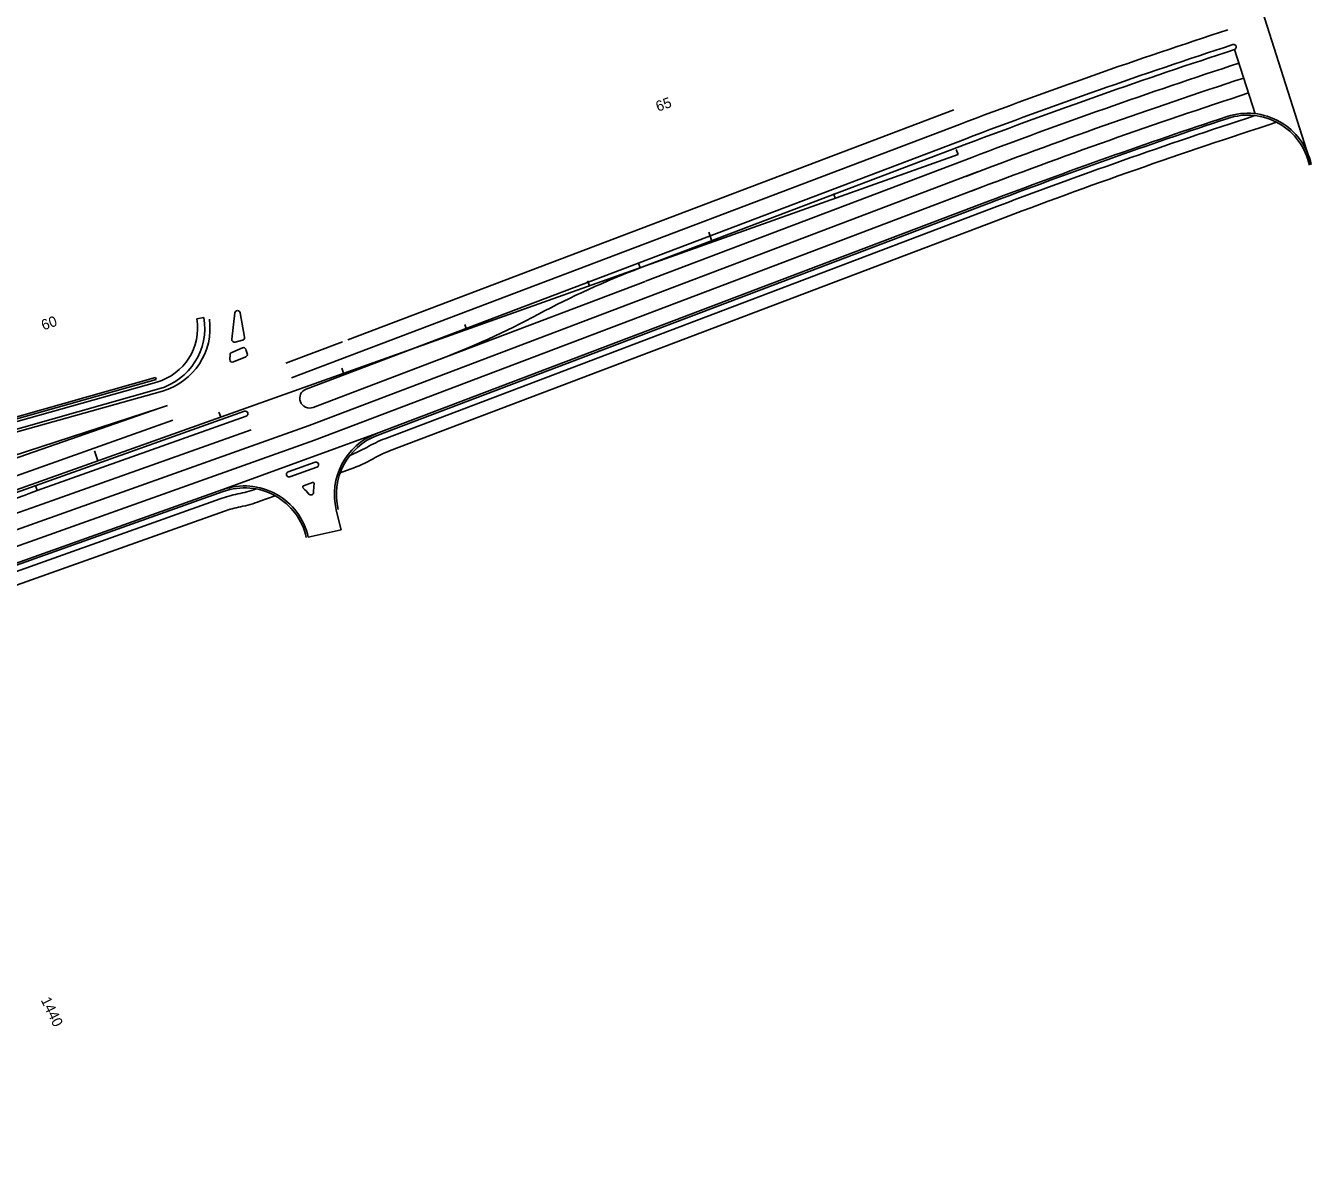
# Model space of a CAD drawing. Extents: x 2339272 to 2351734, y 366540 to 375057.
# Drawn here: x 2350276 to 2351261, y 367900 to 368767 of the extents above; entities that cross this region are included whole.
import ezdxf

# ---------------------------------------------------------------- set-up
doc = ezdxf.new("R2010")
doc.units = 0
for name, color, linetype in [('RD_HC_Cl', 7, 'Continuous'), ('RD_HC_Data_Tic', 7, 'Continuous'), ('RD_HC_TX_Sta50', 7, 'Continuous'), ('RD_PD_ConcMed', 7, 'Continuous'), ('RD_PD_Final_LnLine', 7, 'Continuous'), ('RD_PD_Final_TrvlWay', 7, 'Continuous'), ('RD_PD_FOC', 7, 'Continuous'), ('RD_PD_NOISE-WALL-GM', 7, 'Continuous'), ('RD_PD_SW', 7, 'Continuous')]:
    doc.layers.add(name, color=color, linetype=linetype)

msp = doc.modelspace()

# ---------------------------------------------------------------- linework, layer by layer
at = {"layer": 'RD_HC_Cl'}
msp.add_line((2350026.96, 368325.73), (2350990.33, 368668.55), dxfattribs=at)
msp.add_arc((2351779.88, 368732.45), 1762, 199.58804, 235.18078, dxfattribs=at)
at = {"layer": 'RD_HC_Data_Tic'}
for p, q in [((2350990.33, 368668.55), (2350988.99, 368672.32)), ((2350896.12, 368635.02), (2350894.78, 368638.79)), ((2350801.9, 368601.5), (2350799.22, 368609.04)), ((2350707.69, 368567.97), (2350706.35, 368571.74)), ((2350613.48, 368534.45), (2350612.14, 368538.22)), ((2350519.27, 368500.92), (2350517.92, 368504.69)), ((2350425.05, 368467.4), (2350423.71, 368471.17)), ((2350330.84, 368433.87), (2350328.16, 368441.41))]:
    msp.add_line(p, q, dxfattribs=at)
at = {"layer": 'RD_PD_ConcMed'}
for p, q in [((2350745.27, 368585.41), (2350746.69, 368581.67)), ((2350433.58, 368527.01), (2350435.96, 368547.18)), ((2350443.28, 368528.49), (2350439.91, 368547.3)), ((2350436.03, 368524.83), (2350441.77, 368526.19)), ((2350433.47, 368516.9), (2350441.62, 368520.42)), ((2350444.31, 368519.23), (2350445.39, 368516.06)), ((2350432.27, 368515.19), (2350432.04, 368511.5)), ((2350434.82, 368509.53), (2350444.28, 368513.57)), ((2350284.45, 368411), (2350283.11, 368414.76))]:
    msp.add_line(p, q, dxfattribs=at)
for centre, start, end in [((2350437.95, 368546.95), 10.1289, 173.26408), ((2350435.56, 368526.78), 173.26408, 283.35584), ((2350441.31, 368528.14), 283.35584, 10.1289), ((2350434.27, 368515.06), 113.39418, 176.37352), ((2350442.41, 368518.59), 18.8959, 113.39418), ((2350434.03, 368511.37), 176.37352, 293.08849), ((2350443.5, 368515.41), 293.08849, 18.8959)]:
    msp.add_arc(centre, 2, start, end, dxfattribs=at)
at = {"layer": 'RD_PD_Final_LnLine'}
for p, q in [((2351202.2, 368749), (2351218.22, 368699.85)), ((2350522.45, 368526.52), (2350987.15, 368702.86)), ((2350479.23, 368497.29), (2350991.4, 368691.65)), ((2350490.5, 368488.73), (2350995.66, 368680.43)), ((2350746.69, 368581.67), (2350997.08, 368676.69)), ((2350750.6, 368571.39), (2351000.98, 368666.4)), ((2350492.88, 368460.75), (2351005.24, 368655.18)), ((2350497.02, 368449.49), (2351009.5, 368643.96)), ((2350590.4, 368510.59), (2350750.54, 368571.36)), ((2350474.98, 368508.51), (2350518.4, 368524.98)), ((2350495.82, 368474.7), (2350590.4, 368510.59)), ((2350058.41, 368334.8), (2350443.27, 368471.76)), ((2350284.45, 368411), (2350444.62, 368467.99)), ((2350378.1, 368474.04), (2350384.24, 368476.22)), ((2350023.6, 368335.16), (2350388.26, 368464.92)), ((2350036.68, 368298.41), (2350492.88, 368460.75)), ((2350288.14, 368400.63), (2350448.3, 368457.63)), ((2350040.7, 368287.11), (2350497.02, 368449.49)), ((2350126.71, 368343.19), (2350288.14, 368400.63))]:
    msp.add_line(p, q, dxfattribs=at)
for centre, radius, start, end in [((2352620.61, 364398.39), 4591.99, 108.05731, 110.78079), ((2352620.61, 364398.39), 4579.99, 108.05731, 110.78079), ((2351201.58, 368750.9), 2, 288.05731, 110.01232), ((2352620.61, 364398.39), 4575.99, 108.05731, 110.78079), ((2352620.61, 364398.39), 4564.99, 108.05731, 110.78079), ((2352620.61, 364398.39), 4552.99, 108.05731, 110.9012), ((2352620.61, 364398.39), 4540.99, 108.05731, 110.90467), ((2350984.41, 367955.26), 670, 110.78079, 118.12726), ((2350352.69, 369137.01), 670, 290.78079, 298.12726), ((2350493.16, 368481.72), 7.5, 110.78079, 200.78079), ((2350493.16, 368481.72), 7.5, 200.78079, 290.78079), ((2350443.93, 368469.87), 2, 289.58772, 109.14219), ((2350509.07, 367779.77), 670, 109.58804, 116.93451), ((2351779.88, 368732.45), 1762, 199.58804, 235.18078)]:
    msp.add_arc(centre, radius, start, end, dxfattribs=at)
at = {"layer": 'RD_PD_Final_TrvlWay'}
for p, q in [((2351215.26, 368804.68), (2351261.14, 368660.83)), ((2350544.45, 368454.65), (2351013.75, 368632.74)), ((2350098.11, 368408.37), (2350380.3, 368487.28)), ((2350106.54, 368385.9), (2350378.1, 368474.04)), ((2350108.55, 368380.24), (2350378.1, 368474.04)), ((2350476.73, 368425.28), (2350497.49, 368432.67)), ((2350478.07, 368421.52), (2350498.83, 368428.9)), ((2350157.62, 368315.98), (2350426.54, 368411.67)), ((2350488.54, 368414.63), (2350495.36, 368417.05)), ((2350517.3, 368380.9), (2350513.61, 368396.08)), ((2350492.13, 368375.34), (2350517.3, 368380.9))]:
    msp.add_line(p, q, dxfattribs=at)
for centre, radius, start, end in [((2352620.61, 364398.39), 4528.99, 108.32637, 110.78079), ((2351212.28, 368650.21), 50, 12.2663, 108.32637), ((2350366.84, 368535.44), 50, 285.62317, 8.00142), ((2350562.19, 368407.91), 50, 110.78079, 193.67822), ((2350498.16, 368430.79), 2, 289.58804, 109.58804), ((2350477.4, 368423.4), 2, 109.58804, 289.58804), ((2350443.3, 368364.56), 50, 12.44954, 109.58804), ((2350488.87, 368413.68), 1, 109.58804, 227.14864), ((2350443.3, 368364.56), 66, 41.52414, 47.14864), ((2350494.21, 368409.64), 2, 221.52414, 358.53457), ((2350495.7, 368416.11), 1, 352.96368, 109.58804), ((2350562.19, 368407.91), 66, 172.96368, 178.53457)]:
    msp.add_arc(centre, radius, start, end, dxfattribs=at)
at = {"layer": 'RD_PD_FOC'}
for p, q in [((2350544.98, 368453.25), (2351014.29, 368631.34)), ((2350098.03, 368409.94), (2350377.52, 368488.89)), ((2350158.12, 368314.56), (2350427.04, 368410.26))]:
    msp.add_line(p, q, dxfattribs=at)
for centre, radius, start, end in [((2352620.61, 364398.39), 4527.49, 108.32637, 110.78079), ((2351212.28, 368650.21), 48.5, 12.2663, 108.32637), ((2350364.33, 368535.56), 48.5, 285.77396, 9.46906), ((2350562.19, 368407.91), 48.5, 110.78079, 193.67822), ((2350443.3, 368364.56), 48.5, 12.44954, 109.58804)]:
    msp.add_arc(centre, radius, start, end, dxfattribs=at)
at = {"layer": 'RD_PD_NOISE-WALL-GM'}
for p, q in [((2350094.92, 368418.38), (2350375.07, 368497.55)), ((2350375.07, 368497.55), (2350375.48, 368496.1)), ((2350095.38, 368416.95), (2350375.48, 368496.1))]:
    msp.add_line(p, q, dxfattribs=at)
at = {"layer": 'RD_PD_SW'}
for p, q in [((2350550.98, 368450.71), (2351015.88, 368627.13)), ((2350554.53, 368441.36), (2351019.43, 368617.78)), ((2350406.75, 368542.63), (2350412.17, 368543.54)), ((2350095.99, 368415.05), (2350376.02, 368494.18)), ((2350426.54, 368411.67), (2350544.45, 368454.65)), ((2350516.74, 368424.66), (2350524.36, 368427.37)), ((2350166.99, 368312.94), (2350424.5, 368404.58)), ((2350455.11, 368402.73), (2350466.91, 368406.93)), ((2350170.34, 368303.52), (2350427.86, 368395.16))]:
    msp.add_line(p, q, dxfattribs=at)
for centre, radius, start, end in [((2352620.61, 364398.39), 4522.99, 108.06665, 110.78079), ((2352620.61, 364398.39), 4512.99, 107.8856, 110.78079), ((2350364.33, 368535.56), 43, 285.77396, 9.46906), ((2350586.46, 368357.22), 100, 110.78079, 119.66427), ((2350487.48, 368531.01), 100, 291.50106, 299.66427), ((2350586.46, 368357.22), 90, 110.78079, 119.66427), ((2350487.48, 368531.01), 110, 289.58804, 299.66427), ((2350458.03, 368310.36), 100, 101.47842, 109.58804), ((2350418.23, 368506.36), 100, 281.47842, 289.78076), ((2350458.03, 368310.36), 90, 101.47842, 109.58804), ((2350418.23, 368506.36), 110, 281.47842, 289.58804)]:
    msp.add_arc(centre, radius, start, end, dxfattribs=at)

# ---------------------------------------------------------------- texts
at = {"layer": 'RD_HC_TX_Sta50'}
for s, rotation, p in [('65', 19.58804, (2350760.27, 368701.32)), ('60', 19.58804, (2350289.17, 368533.68)), ('1440', 295.90041, (2350286.92, 368020.47))]:
    msp.add_text(s, height=8, rotation=rotation, dxfattribs=at).set_placement(p)

doc.saveas('drawing.dxf')
